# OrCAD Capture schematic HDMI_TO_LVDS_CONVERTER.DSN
size B
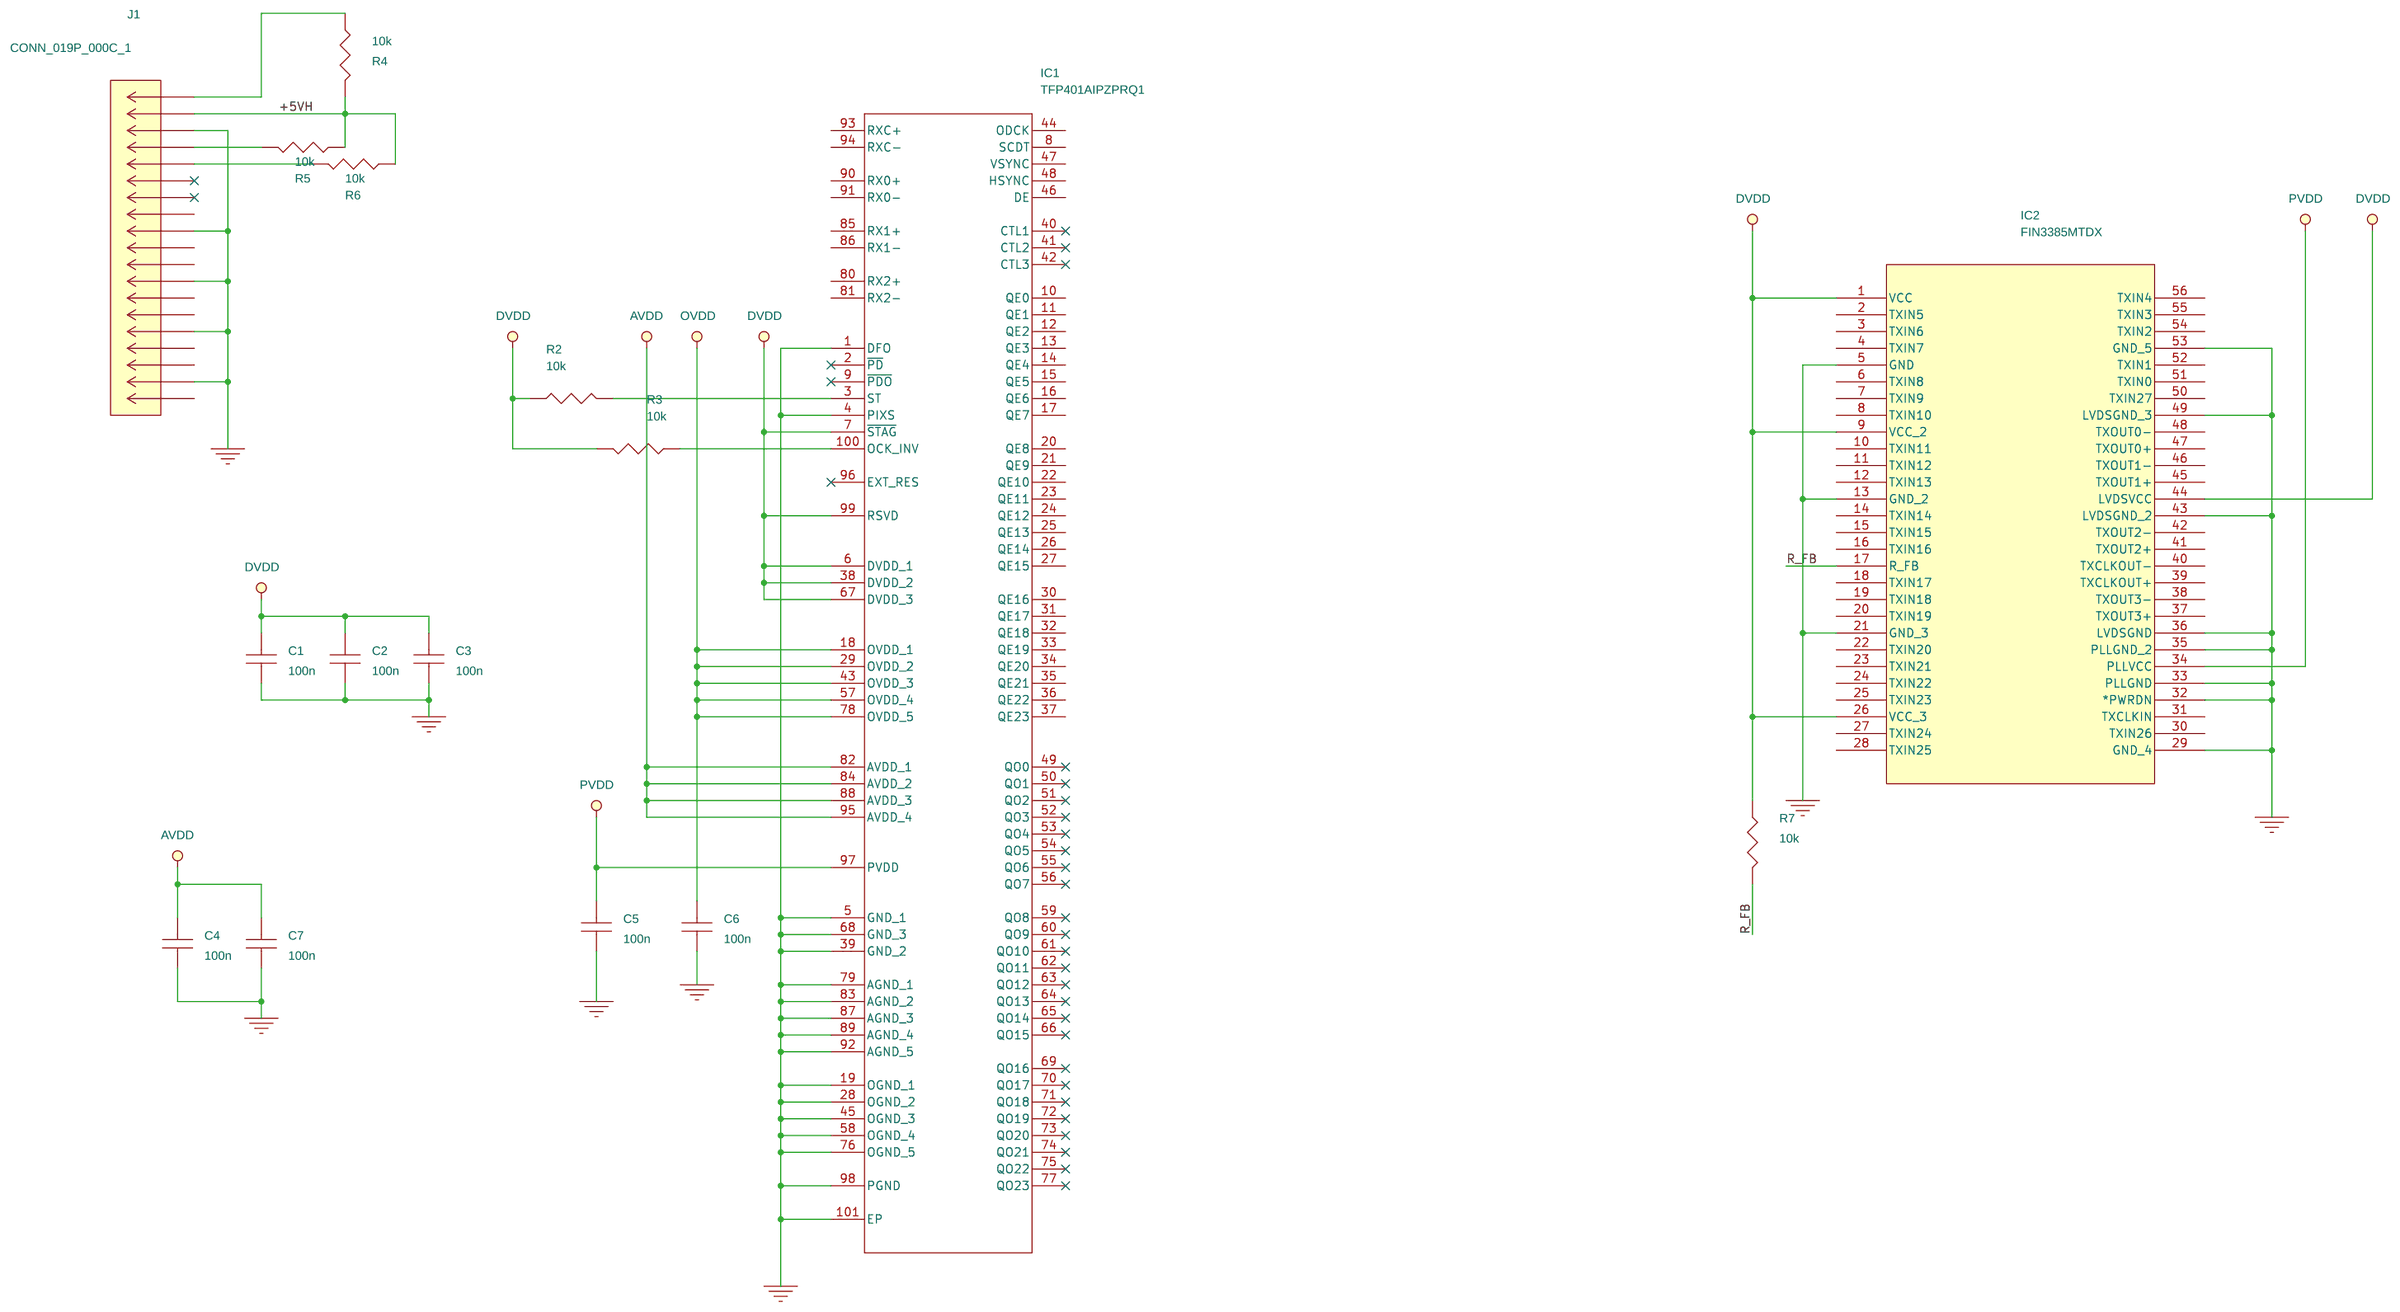
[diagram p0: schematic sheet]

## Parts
C1  100n  [SMC0603]
C2  100n  [SMC0603]
C3  100n  [SMC0603]
C4  100n  [SMC0603]
C5  100n  [SMC0603]
C6  100n  [SMC0603]
C7  100n  [SMC0603]
IC1  TFP401AIPZPRQ1  [QFP50P1600X1600X120-101N]
IC2  FIN3385MTDX  [TSSOP56_6P1X14_ONS]
J1  CONN_019P_000C_1  [CONN_208658-1051_MOL]
R2  10k  [SMR0603]
R3  10k  [SMR0603]
R4  10k  [SMR0603]
R5  10k  [SMR0603]
R6  10k  [SMR0603]
R7  10k  [SMR0603]

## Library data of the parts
C1-C7 = CAP_NP: Room: Amplifier
IC1 = TFP401AIPZPRQ1_1: Manufacturer Name: Texas Instruments; Source Id: SamacSys
IC2 = FIN3385MTDX: Manufacturer Name: onsemi; Source Id: UL
J1 = 2086581051: Manufacturer Name: Molex Connector Corporation; Source Id: UL
R2-R7 = RESISTOR: Room: Power

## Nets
+5VH: J1.18 R4.1 R5.2 R6.2
AVDD: C4.2 C7.2 IC1.82(AVDD_1) IC1.84(AVDD_2) IC1.88(AVDD_3) IC1.95(AVDD_4)
DVDD: C1.2 C2.2 C3.2 IC1.6(DVDD_1) IC1.7(~{STAG}) IC1.38(DVDD_2) IC1.67(DVDD_3) IC1.99(RSVD) IC2.1(VCC) IC2.9(VCC_2) IC2.26(VCC_3) IC2.44(LVDSVCC) R2.1 R3.2 R7.1
PVDD: C5.2 IC1.97(PVDD) IC2.34(PLLVCC)
0: C1.1 C2.1 C3.1 C4.1 C5.1 C6.1 C7.1 IC1.1(DFO) IC1.4(PIXS) IC1.5(GND_1) IC1.19(OGND_1) IC1.28(OGND_2) IC1.39(GND_2) IC1.45(OGND_3) IC1.58(OGND_4) IC1.68(GND_3) IC1.76(OGND_5) IC1.79(AGND_1) IC1.83(AGND_2) IC1.87(AGND_3) IC1.89(AGND_4) IC1.92(AGND_5) IC1.98(PGND) IC1.101(EP) IC2.5(GND) IC2.13(GND_2) IC2.21(GND_3) IC2.29(GND_4) IC2.32(*PWRDN) IC2.33(PLLGND) IC2.35(PLLGND_2) IC2.36(LVDSGND) IC2.43(LVDSGND_2) IC2.49(LVDSGND_3) IC2.53(GND_5) J1.2 J1.5 J1.8 J1.11 J1.17
OVDD: C6.2 IC1.18(OVDD_1) IC1.29(OVDD_2) IC1.43(OVDD_3) IC1.57(OVDD_4) IC1.78(OVDD_5)
R_FB: IC2.17(R_FB) R7.2
N10505: IC1.3(ST) R2.2
N10593: IC1.100(OCK_INV) R3.1
N12618: J1.19 R4.2
N12702: J1.16 R5.1
N12736: J1.15 R6.1

Not connected (* = marked no-connect by the designer): IC1 2(~{PD})* 8(SCDT) 9(~{PDO})* 10(QE0) 11(QE1) 12(QE2) 13(QE3) 14(QE4) 15(QE5) 16(QE6) 17(QE7) 20(QE8) 21(QE9) 22(QE10) 23(QE11) 24(QE12) 25(QE13) 26(QE14) 27(QE15) 30(QE16) 31(QE17) 32(QE18) 33(QE19) 34(QE20) 35(QE21) 36(QE22) 37(QE23) 40(CTL1)* 41(CTL2)* 42(CTL3)* 44(ODCK) 46(DE) 47(VSYNC) 48(HSYNC) 49(QO0)* 50(QO1)* 51(QO2)* 52(QO3)* 53(QO4)* 54(QO5)* 55(QO6)* 56(QO7)* 59(QO8)* 60(QO9)* 61(QO10)* 62(QO11)* 63(QO12)* 64(QO13)* 65(QO14)* 66(QO15)* 69(QO16)* 70(QO17)* 71(QO18)* 72(QO19)* 73(QO20)* 74(QO21)* 75(QO22)* 77(QO23)* 80(RX2+) 81(RX2-) 85(RX1+) 86(RX1-) 90(RX0+) 91(RX0-) 93(RXC+) 94(RXC-) 96(EXT_RES)*; IC2 2(TXIN5) 3(TXIN6) 4(TXIN7) 6(TXIN8) 7(TXIN9) 8(TXIN10) 10(TXIN11) 11(TXIN12) 12(TXIN13) 14(TXIN14) 15(TXIN15) 16(TXIN16) 18(TXIN17) 19(TXIN18) 20(TXIN19) 22(TXIN20) 23(TXIN21) 24(TXIN22) 25(TXIN23) 27(TXIN24) 28(TXIN25) 30(TXIN26) 31(TXCLKIN) 37(TXOUT3+) 38(TXOUT3-) 39(TXCLKOUT+) 40(TXCLKOUT-) 41(TXOUT2+) 42(TXOUT2-) 45(TXOUT1+) 46(TXOUT1-) 47(TXOUT0+) 48(TXOUT0-) 50(TXIN27) 51(TXIN0) 52(TXIN1) 54(TXIN2) 55(TXIN3) 56(TXIN4); J1 1 3 4 6 7 9 10 12 13* 14*
